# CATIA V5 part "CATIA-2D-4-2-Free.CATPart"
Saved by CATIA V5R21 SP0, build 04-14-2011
Part number: CATIA-2D-4-2-Free
Bounding box of the stored display mesh (mm): x -48.656 to 64.999, y 0 to 0, z -29.982 to 126.918
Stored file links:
  C:\Users\Rasoul Mohammadi\Desktop\CATIA-Free\2D\CATIA-2D-4-2-Free.CATPart
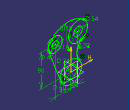
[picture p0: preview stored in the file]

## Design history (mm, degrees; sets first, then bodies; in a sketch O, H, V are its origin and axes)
Body1 (main body)
  Sketch1 on zx-plane, origin (0, 0, 0), H (-1, 0, 0), V (0, 0, 1)
    circle A1 centre (0, 0) radius 30
    circle A2 centre (0, 0) radius 17
    circle A3 centre (-45, 90) radius 9
    point P1 (-45, 90)
    circle A4 centre (-45, 90) radius 20
    circle A5 centre (20, 90) radius 12
    point P2 (20, 90)
    circle A6 centre (20, 90) radius 27
    arc A7 centre (-7.4923, 56.9368) radius 70 from (-60.0031, 103.2253) to (37.2626, 110.7606) cw
    point P4 (-60.0031, 103.2253)
    point P5 (37.2626, 110.7606)
    line L1 (-63.6889, 82.8778) -> (-28.0333, -10.6833)
    point P6 (-63.6889, 82.8778)
    point P7 (-28.0333, -10.6833)
    arc A8 centre (48.656, 38.4264) radius 32 from (33.1138, 66.3985) to (23.5432, 18.5934) ccw
    point P9 (33.1138, 66.3985)
    point P10 (23.5432, 18.5934)
    axis line L2 (20, 90) -> (-45, 90)
    radius A1 = 30
    radius A6 = 27
    radius A4 = 20
    radius A3 = 9
    radius A2 = 17
    radius A5 = 12
    distance V P2 = 20
    distance V P1 = 45
    distance P1 H = 90
    radius A7 = 70
    radius A8 = 32
    coincidence: P4 A4, P5 A6, P6 A4, P9 A6, P10 A1, P7 A1
    tangency: A7 A4, L1 A1, A7 A6, L1 A4, A8 A6, A1 A8
    horizontal: L2 H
